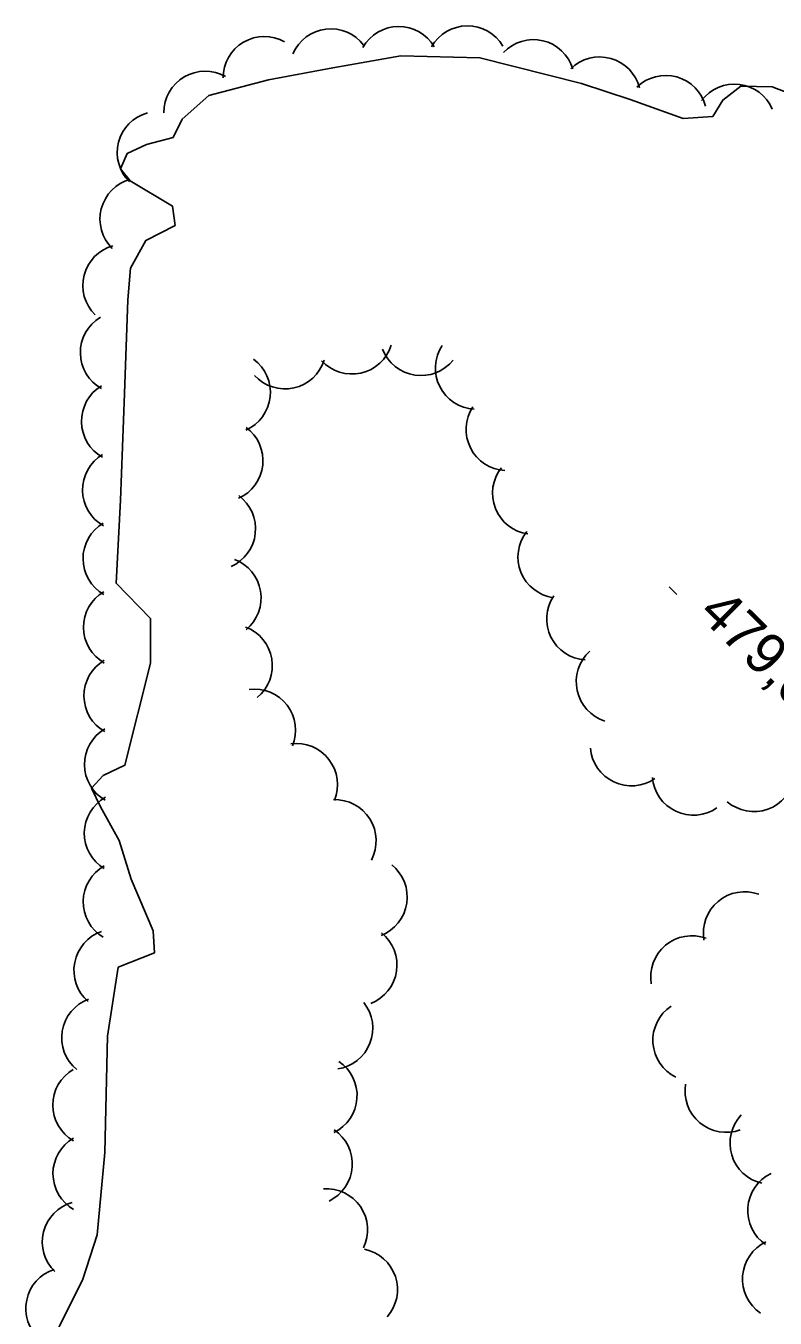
# Model space of a CAD drawing. Extents: x 642515 to 647219, y 6080136 to 6084356.
# Drawn here: x 643763.3 to 643817.9, y 6082247.3 to 6082341.5 of the extents above; entities that cross this region are included whole.
import ezdxf

# ---------------------------------------------------------------- set-up
doc = ezdxf.new("R2010")
doc.units = 0
for name, color, linetype in [('Level 3', 7, 'Continuous'), ('Level 4', 7, 'Continuous'), ('Level 44', 7, 'Continuous')]:
    doc.layers.add(name, color=color, linetype=linetype)

msp = doc.modelspace()

# ---------------------------------------------------------------- linework, layer by layer
at = {"layer": 'Level 3'}
msp.add_line((643810.181, 6082300.624), (643810.752, 6082300.064), dxfattribs=at)
at = {"layer": 'Level 4'}
for points in [[(643820.805, 6082335.841), (643817.681, 6082337.026), (643815.395, 6082337.071), (643814.104, 6082336.065), (643813.353, 6082334.883), (643811.2, 6082334.73), (643807.331, 6082336.122), (643803.8, 6082337.285), (643796.398, 6082339.147), (643790.639, 6082339.297), (643785.67, 6082338.427), (643780.988, 6082337.531), (643776.645, 6082336.407), (643774.702, 6082334.674), (643774.042, 6082333.333), (643772.112, 6082332.825), (643770.68, 6082332.179), (643770.212, 6082331.053), (643770.912, 6082330.191), (643773.991, 6082328.351), (643774.191, 6082326.933), (643772.049, 6082325.842), (643770.937, 6082323.825), (643770.738, 6082321.529), (643770.503, 6082314.702), (643770.198, 6082306.934), (643769.881, 6082300.879), (643772.387, 6082298.317), (643772.404, 6082295.054), (643770.532, 6082287.615), (643768.942, 6082286.88), (643768.097, 6082285.939), (643768.743, 6082284.585), (643770.102, 6082282.127)], [(643770.102, 6082282.127), (643770.991, 6082279.319), (643772.584, 6082275.568), (643772.674, 6082273.942), (643770.04, 6082272.908), (643769.258, 6082267.893), (643769.075, 6082259.403), (643768.509, 6082253.423), (643767.465, 6082250.189), (643764.019, 6082243.244)]]:
    msp.add_lwpolyline(points, dxfattribs=at)
at = {"layer": 'Level 44'}
for centre, start, end in [((643795.484, 6082338.475), 30.51261, 150.49056), ((643780.681, 6082337.698), 60.38107, 180.35901), ((643785.525, 6082338.259), 36.70952, 156.68747), ((643790.484, 6082338.432), 30.51261, 150.49056), ((643800.295, 6082337.472), 16.79635, 136.77429), ((643805.119, 6082336.209), 14.46746, 134.44541), ((643776.367, 6082335.17), 60.38107, 180.35901), ((643809.936, 6082334.868), 14.46746, 134.44541), ((643814.939, 6082334.235), 23.07855, 143.05649), ((643772.964, 6082332.243), 105.52039, 225.49834), ((643771.712, 6082327.402), 105.52039, 225.49834), ((643770.46, 6082322.562), 105.52039, 225.49834), ((643770.282, 6082317.674), 120.90833, 240.88627), ((643787.07, 6082319.113), 222.51039, 342.48833), ((643796.147, 6082316.543), 146.65184, 266.62978), ((643778.128, 6082314.774), 293.81254, 53.79048), ((643782.188, 6082318.032), 222.51039, 342.48833), ((643792.101, 6082319.003), 201.26106, 321.23901), ((643770.359, 6082312.674), 120.90833, 240.88627), ((643798.388, 6082312.073), 146.65184, 266.62978), ((643777.587, 6082309.804), 293.81254, 53.79048), ((643770.437, 6082307.675), 120.90833, 240.88627), ((643800.312, 6082307.433), 141.80291, 261.78086), ((643777.046, 6082304.833), 293.81254, 53.79048), ((643770.474, 6082302.672), 120.42572, 240.40366), ((643802.167, 6082302.79), 141.80291, 261.78086), ((643777.452, 6082299.807), 309.4189, 69.39685), ((643770.509, 6082297.673), 120.42572, 240.40366), ((643804.262, 6082298.279), 146.24048, 266.21843), ((643778.269, 6082294.874), 309.4189, 69.39685), ((643806.411, 6082293.695), 132.26265, 252.2406), ((643770.544, 6082292.673), 120.42572, 240.40366), ((643779.967, 6082290.166), 337.60913, 97.58708), ((643770.58, 6082287.673), 120.42572, 240.40366), ((643783.017, 6082286.203), 337.60913, 97.58708), ((643807.43, 6082289.115), 184.69453, 304.67248), ((643811.949, 6082286.976), 184.69453, 304.67248), ((643816.362, 6082287.241), 229.50617, 349.48411), ((643770.566, 6082282.666), 119.10153, 239.07948), ((643785.833, 6082282.114), 332.0855, 92.06344), ((643770.486, 6082277.667), 119.10153, 239.07948), ((643788.097, 6082278.008), 291.42657, 51.40452), ((643815.674, 6082275.4), 69.84918, 189.82713), ((643769.813, 6082272.676), 109.13229, 229.11023), ((643787.35, 6082273.065), 291.42657, 51.40452), ((643811.834, 6082272.198), 69.84918, 189.82713), ((643768.922, 6082267.764), 110.4985, 230.47645), ((643785.591, 6082268.462), 278.56586, 38.54381), ((643811.995, 6082267.582), 123.91009, 243.88803), ((643768.273, 6082262.869), 120.16713, 240.14508), ((643784.444, 6082263.561), 296.0042, 55.98214), ((643814.339, 6082263.876), 170.00686, 289.98481), ((643817.616, 6082260.091), 136.71131, 256.68926), ((643784.094, 6082258.573), 296.0042, 55.98214), ((643768.285, 6082257.869), 120.16713, 240.14508), ((643818.906, 6082255.176), 115.67227, 235.65021), ((643785.212, 6082253.778), 334.24099, 94.21894), ((643767.508, 6082252.891), 105.91341, 225.89136), ((643787.389, 6082249.421), 318.51235, 78.4903), ((643818.527, 6082250.191), 115.67227, 235.65021), ((643766.309, 6082248.05), 108.30998, 228.28792)]:
    msp.add_arc(centre, 3, start, end, dxfattribs=at)

# ---------------------------------------------------------------- texts
at = {"layer": 'Level 3'}
msp.add_text('479,0', height=3, rotation=315.59, dxfattribs=at).set_placement((643812.21, 6082298.58))

doc.saveas('drawing.dxf')
